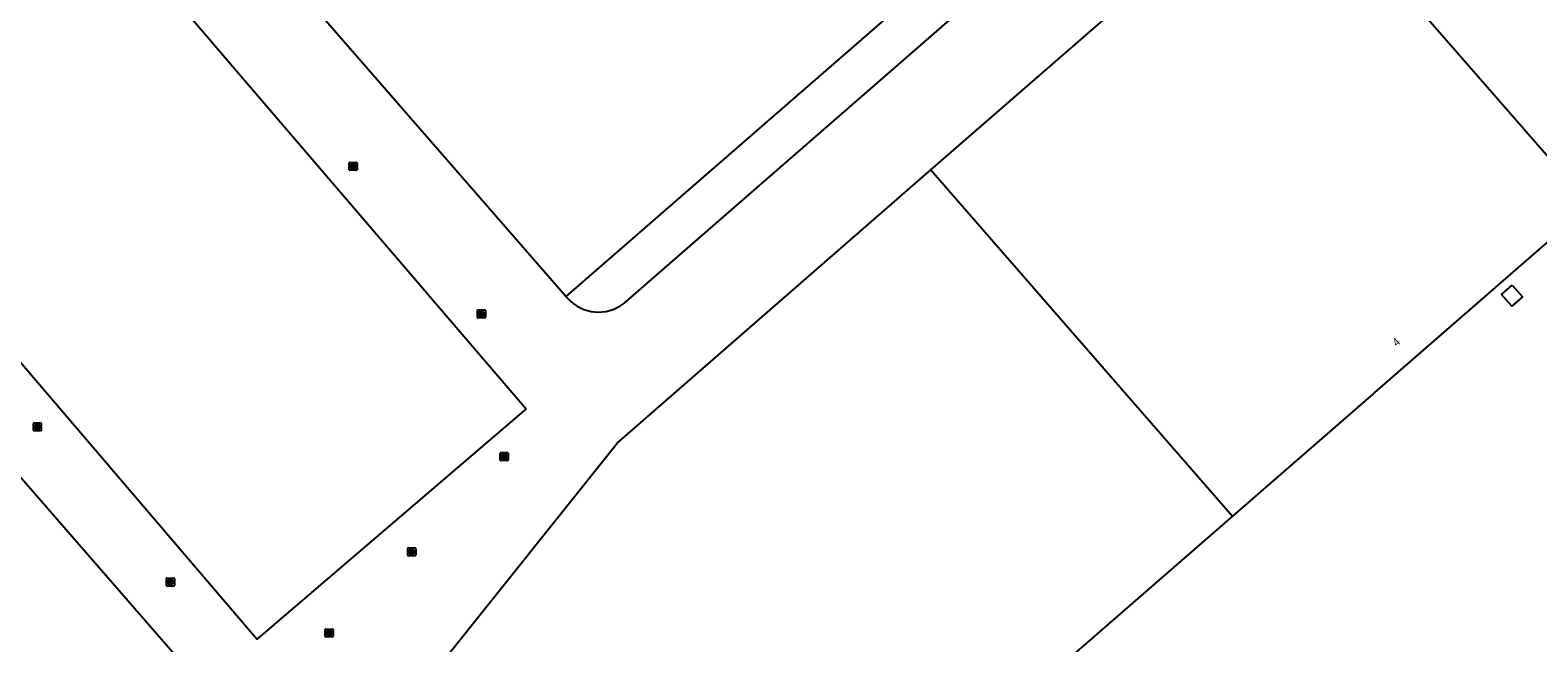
# Model space of a CAD drawing. Extents: x 156141 to 158132, y 385651 to 388399.
# Drawn here: x 156511.2 to 156702, y 386748.9 to 386826.5 of the extents above; entities that cross this region are included whole.
import ezdxf

# ---------------------------------------------------------------- set-up
doc = ezdxf.new("R2010")
doc.units = 0
for name, color, linetype in [('IMGEO_Kolk', 7, 'Continuous'), ('IMGEO_Pand', 7, 'Continuous'), ('IMGEO_Pand_nummerreeks', 7, 'Continuous'), ('IMGEO_Pand_overbouw', 7, 'Continuous')]:
    doc.layers.add(name, color=color, linetype=linetype)

msp = doc.modelspace()

# ---------------------------------------------------------------- linework, layer by layer
at = {"layer": 'IMGEO_Kolk'}
for p, q in [((156551.56, 386808.8), (156551.56, 386809.65)), ((156551.64, 386809.72), (156552.49, 386809.72)), ((156552.05, 386809.5), (156552.08, 386809.5)), ((156552.56, 386809.65), (156552.56, 386808.8)), ((156552.49, 386808.72), (156551.64, 386808.72)), ((156552.07, 386808.94), (156552.05, 386808.94)), ((156567.8, 386790.11), (156567.8, 386790.96)), ((156567.87, 386791.04), (156568.72, 386791.04)), ((156568.72, 386790.04), (156567.87, 386790.04)), ((156568.28, 386790.82), (156568.31, 386790.82)), ((156568.31, 386790.26), (156568.28, 386790.26)), ((156568.8, 386790.96), (156568.8, 386790.11)), ((156511.6, 386775.82), (156511.6, 386776.67)), ((156511.67, 386776.74), (156512.52, 386776.74)), ((156512.6, 386776.67), (156512.6, 386775.82)), ((156512.52, 386775.74), (156511.67, 386775.74)), ((156512.11, 386775.96), (156512.08, 386775.96)), ((156512.09, 386776.52), (156512.11, 386776.52)), ((156570.68, 386772.05), (156570.68, 386772.9)), ((156570.75, 386772.98), (156571.6, 386772.98)), ((156571.68, 386772.9), (156571.68, 386772.05)), ((156571.6, 386771.98), (156570.75, 386771.98)), ((156571.16, 386772.76), (156571.19, 386772.76)), ((156571.19, 386772.2), (156571.16, 386772.2)), ((156558.98, 386759.99), (156558.98, 386760.84)), ((156559.06, 386760.92), (156559.91, 386760.92)), ((156559.91, 386759.92), (156559.06, 386759.92)), ((156559.47, 386760.7), (156559.5, 386760.7)), ((156559.49, 386760.14), (156559.47, 386760.14)), ((156559.98, 386760.84), (156559.98, 386759.99)), ((156528.44, 386756.16), (156528.44, 386757.01)), ((156528.51, 386757.08), (156529.36, 386757.08)), ((156529.36, 386756.08), (156528.51, 386756.08)), ((156528.92, 386756.86), (156528.95, 386756.86)), ((156528.95, 386756.3), (156528.92, 386756.3)), ((156529.44, 386757.01), (156529.44, 386756.16)), ((156548.54, 386749.71), (156548.54, 386750.57)), ((156548.61, 386750.64), (156549.47, 386750.64)), ((156549.03, 386750.42), (156549.05, 386750.42)), ((156549.54, 386750.57), (156549.54, 386749.71)), ((156549.47, 386749.64), (156548.61, 386749.64)), ((156549.05, 386749.86), (156549.02, 386749.86))]:
    msp.add_line(p, q, dxfattribs=at)
for points in [[(156551.56, 386808.8), (156551.56, 386809.65)], [(156551.64, 386809.72), (156552.49, 386809.72)], [(156551.88, 386809.42), (156552.01, 386809.42), (156552.01, 386809.27), (156552.14, 386809.42), (156552.3, 386809.42), (156552.15, 386809.27), (156552.31, 386809.02), (156552.15, 386809.02), (156552.07, 386809.19), (156552.01, 386809.12), (156552.01, 386809.02), (156551.88, 386809.02), (156551.88, 386809.42)], [(156552.56, 386809.65), (156552.56, 386808.8)], [(156552.49, 386808.72), (156551.64, 386808.72)], [(156567.8, 386790.11), (156567.8, 386790.96)], [(156567.87, 386791.04), (156568.72, 386791.04)], [(156568.72, 386790.04), (156567.87, 386790.04)], [(156568.12, 386790.74), (156568.24, 386790.74), (156568.24, 386790.58), (156568.37, 386790.74), (156568.53, 386790.74), (156568.39, 386790.59), (156568.54, 386790.34), (156568.39, 386790.34), (156568.3, 386790.5), (156568.24, 386790.43), (156568.24, 386790.34), (156568.12, 386790.34), (156568.12, 386790.74)], [(156568.8, 386790.96), (156568.8, 386790.11)], [(156511.6, 386775.82), (156511.6, 386776.67)], [(156511.67, 386776.74), (156512.52, 386776.74)], [(156512.6, 386776.67), (156512.6, 386775.82)], [(156512.52, 386775.74), (156511.67, 386775.74)], [(156511.92, 386776.44), (156512.04, 386776.44), (156512.04, 386776.29), (156512.17, 386776.44), (156512.34, 386776.44), (156512.19, 386776.29), (156512.34, 386776.04), (156512.19, 386776.04), (156512.11, 386776.21), (156512.04, 386776.14), (156512.04, 386776.04), (156511.92, 386776.04), (156511.92, 386776.44)], [(156570.68, 386772.05), (156570.68, 386772.9)], [(156570.75, 386772.98), (156571.6, 386772.98)], [(156571.68, 386772.9), (156571.68, 386772.05)], [(156571.6, 386771.98), (156570.75, 386771.98)], [(156571, 386772.68), (156571.12, 386772.68), (156571.12, 386772.53), (156571.25, 386772.68), (156571.41, 386772.68), (156571.27, 386772.53), (156571.42, 386772.28), (156571.27, 386772.28), (156571.18, 386772.44), (156571.12, 386772.37), (156571.12, 386772.28), (156571, 386772.28), (156571, 386772.68)], [(156558.98, 386759.99), (156558.98, 386760.84)], [(156559.06, 386760.92), (156559.91, 386760.92)], [(156559.91, 386759.92), (156559.06, 386759.92)], [(156559.3, 386760.62), (156559.43, 386760.62), (156559.43, 386760.47), (156559.56, 386760.62), (156559.72, 386760.62), (156559.57, 386760.47), (156559.73, 386760.22), (156559.57, 386760.22), (156559.49, 386760.38), (156559.43, 386760.31), (156559.43, 386760.22), (156559.3, 386760.22), (156559.3, 386760.62)], [(156559.98, 386760.84), (156559.98, 386759.99)], [(156528.44, 386756.16), (156528.44, 386757.01)], [(156528.51, 386757.08), (156529.36, 386757.08)], [(156529.36, 386756.08), (156528.51, 386756.08)], [(156528.76, 386756.78), (156528.88, 386756.78), (156528.88, 386756.63), (156529.01, 386756.78), (156529.17, 386756.78), (156529.03, 386756.63), (156529.18, 386756.38), (156529.03, 386756.38), (156528.94, 386756.55), (156528.88, 386756.48), (156528.88, 386756.38), (156528.76, 386756.38), (156528.76, 386756.78)], [(156529.44, 386757.01), (156529.44, 386756.16)], [(156548.54, 386749.71), (156548.54, 386750.57)], [(156548.61, 386750.64), (156549.47, 386750.64)], [(156548.86, 386750.34), (156548.98, 386750.34), (156548.98, 386750.19), (156549.11, 386750.34), (156549.28, 386750.34), (156549.13, 386750.19), (156549.28, 386749.94), (156549.13, 386749.94), (156549.05, 386750.1), (156548.98, 386750.04), (156548.98, 386749.94), (156548.86, 386749.94), (156548.86, 386750.34)], [(156549.54, 386750.57), (156549.54, 386749.71)], [(156549.47, 386749.64), (156548.61, 386749.64)]]:
    msp.add_lwpolyline(points, dxfattribs=at)
for centre, start, end in [((156551.64, 386809.65), 91.552, 178.448), ((156551.64, 386809.65), 91.552, 178.448), ((156552.49, 386809.65), 1.552, 88.448), ((156552.49, 386809.65), 1.552, 88.448), ((156551.64, 386808.8), 181.552, 268.448), ((156551.64, 386808.8), 181.552, 268.448), ((156552.49, 386808.8), 271.552, 358.448), ((156552.49, 386808.8), 271.552, 358.448), ((156567.87, 386790.96), 91.552, 178.448), ((156567.87, 386790.96), 91.552, 178.448), ((156567.87, 386790.11), 181.552, 268.448), ((156567.87, 386790.11), 181.552, 268.448), ((156568.72, 386790.96), 1.552, 88.448), ((156568.72, 386790.96), 1.552, 88.448), ((156568.72, 386790.11), 271.552, 358.448), ((156568.72, 386790.11), 271.552, 358.448), ((156511.67, 386776.67), 91.552, 178.448), ((156511.67, 386776.67), 91.552, 178.448), ((156512.52, 386776.67), 1.552, 88.448), ((156512.52, 386776.67), 1.552, 88.448), ((156511.67, 386775.82), 181.552, 268.448), ((156511.67, 386775.82), 181.552, 268.448), ((156512.52, 386775.82), 271.552, 358.448), ((156512.52, 386775.82), 271.552, 358.448), ((156570.75, 386772.9), 91.552, 178.448), ((156570.75, 386772.9), 91.552, 178.448), ((156571.6, 386772.9), 1.552, 88.448), ((156571.6, 386772.9), 1.552, 88.448), ((156570.75, 386772.05), 181.552, 268.448), ((156570.75, 386772.05), 181.552, 268.448), ((156571.6, 386772.05), 271.552, 358.448), ((156571.6, 386772.05), 271.552, 358.448), ((156559.06, 386760.84), 91.552, 178.448), ((156559.06, 386760.84), 91.552, 178.448), ((156559.06, 386759.99), 181.552, 268.448), ((156559.06, 386759.99), 181.552, 268.448), ((156559.91, 386760.84), 1.552, 88.448), ((156559.91, 386760.84), 1.552, 88.448), ((156559.91, 386759.99), 271.552, 358.448), ((156559.91, 386759.99), 271.552, 358.448), ((156528.51, 386757.01), 91.552, 178.448), ((156528.51, 386757.01), 91.552, 178.448), ((156528.51, 386756.16), 181.552, 268.448), ((156528.51, 386756.16), 181.552, 268.448), ((156529.36, 386757.01), 1.552, 88.448), ((156529.36, 386757.01), 1.552, 88.448), ((156529.36, 386756.16), 271.552, 358.448), ((156529.36, 386756.16), 271.552, 358.448), ((156548.61, 386750.56), 91.552, 178.448), ((156548.61, 386750.56), 91.552, 178.448), ((156549.46, 386750.56), 1.552, 88.448), ((156549.46, 386750.56), 1.552, 88.448), ((156548.61, 386749.71), 181.552, 268.448), ((156548.61, 386749.71), 181.552, 268.448), ((156549.46, 386749.71), 271.552, 358.448), ((156549.46, 386749.71), 271.552, 358.448)]:
    msp.add_arc(centre, 0.0765, start, end, dxfattribs=at)
for centre, major_axis, ratio, start_param, end_param in [((156552.05, 386809.22), (-0.387, 0.002), 0.722429, 4.712389, 7.853982), ((156552.07, 386809.22), (-0.39, 0.002), 0.717154, 1.570796, 4.712389), ((156568.28, 386790.54), (-0.387, 0.002), 0.722429, 4.712389, 7.853982), ((156568.31, 386790.54), (-0.39, 0.002), 0.717154, 1.570796, 4.712389), ((156512.08, 386776.24), (-0.387, 0.002), 0.722429, 4.712389, 7.853982), ((156512.11, 386776.24), (-0.39, 0.002), 0.717154, 1.570796, 4.712389), ((156571.16, 386772.48), (-0.387, 0.002), 0.722429, 4.712389, 7.853982), ((156571.19, 386772.48), (-0.39, 0.002), 0.717154, 1.570796, 4.712389), ((156559.47, 386760.42), (-0.387, 0.002), 0.722429, 4.712389, 7.853982), ((156559.49, 386760.42), (-0.39, 0.002), 0.717154, 1.570796, 4.712389), ((156528.92, 386756.58), (-0.387, 0.002), 0.722429, 4.712389, 7.853982), ((156528.95, 386756.58), (-0.39, 0.002), 0.717154, 1.570796, 4.712389), ((156549.03, 386750.14), (-0.387, 0.002), 0.722429, 4.712389, 7.853982), ((156549.05, 386750.14), (-0.39, 0.002), 0.717154, 1.570796, 4.712389)]:
    msp.add_ellipse(centre, major_axis=major_axis, ratio=ratio, start_param=start_param, end_param=end_param, dxfattribs=at)
at = {"layer": 'IMGEO_Pand'}
for points in [[(156579, 386792.74), (156536.65, 386841.45), (156528.4, 386850.93), (156539.01, 386860.16), (156540.51, 386861.46), (156539.64, 386862.47), (156541.88, 386864.4), (156542.76, 386863.4), (156544.26, 386864.71), (156553.86, 386857.56), (156554.4, 386856.9), (156564.64, 386845.13), (156582.75, 386860.85), (156583.79, 386861.76), (156573.53, 386873.55), (156565.27, 386883.02), (156568.32, 386885.63), (156567.99, 386886), (156571.25, 386888.77), (156592.61, 386907.35), (156643.5, 386848.89), (156579, 386792.74)], [(156625.19, 386808.77), (156670.44, 386848.17)], [(156670.44, 386848.17), (156708.6, 386804.34)], [(156573.96, 386778.5), (156540.63, 386750), (156539.88, 386749.35), (156539.32, 386750), (156500.02, 386795.98), (156500.69, 386796.56), (156500.87, 386796.72), (156507.65, 386802.53), (156507.84, 386802.69), (156508.6, 386803.34), (156500, 386813.38), (156498.7, 386814.9), (156500, 386815.99), (156501.01, 386816.84), (156500, 386818.01), (156497.07, 386821.42), (156500, 386824.27), (156502.48, 386826.69), (156506.95, 386831.05), (156513.62, 386837.54), (156518.51, 386831.86), (156524.17, 386836.69), (156573.96, 386778.5)], [(156562.82, 386745.82), (156585.47, 386774.18), (156625.19, 386808.77)], [(156625.19, 386808.77), (156663.35, 386764.94)], [(156708.6, 386804.34), (156681.33, 386780.59), (156681.14, 386780.43), (156663.35, 386764.94)], [(156698.75, 386794.18), (156700.06, 386792.68), (156698.71, 386791.5), (156697.4, 386793), (156698.75, 386794.18)], [(156497.13, 386765.98), (156498.54, 386767.48), (156505.52, 386774.95), (156539.63, 386735.79), (156502.86, 386689.7), (156473.05, 386707.68), (156477.03, 386711.95), (156467.31, 386721.05), (156467.13, 386720.89), (156467.24, 386720.39)], [(156663.35, 386764.94), (156635.2, 386740.45), (156635.02, 386740.29), (156627.59, 386733.83), (156608.17, 386709.52)]]:
    msp.add_lwpolyline(points, dxfattribs=at)
at = {"layer": 'IMGEO_Pand_overbouw'}
msp.add_lwpolyline([(156643.5, 386848.89), (156579, 386792.74), (156579.31, 386792.39), (156579.65, 386792.07), (156580.02, 386791.78), (156580.42, 386791.52), (156580.83, 386791.3), (156581.27, 386791.11), (156581.71, 386790.97), (156582.17, 386790.86), (156582.64, 386790.8), (156583.11, 386790.78), (156583.58, 386790.8), (156584.05, 386790.86), (156584.51, 386790.96), (156584.96, 386791.11), (156585.39, 386791.29), (156585.81, 386791.51), (156586.2, 386791.77), (156586.57, 386792.06), (156643.21, 386841.38)], dxfattribs=at)

# ---------------------------------------------------------------- texts
at = {"layer": 'IMGEO_Pand_nummerreeks'}
msp.add_text('4', height=1, rotation=41.0387, dxfattribs=at).set_placement((156684.12, 386786.36))

doc.saveas('drawing.dxf')
